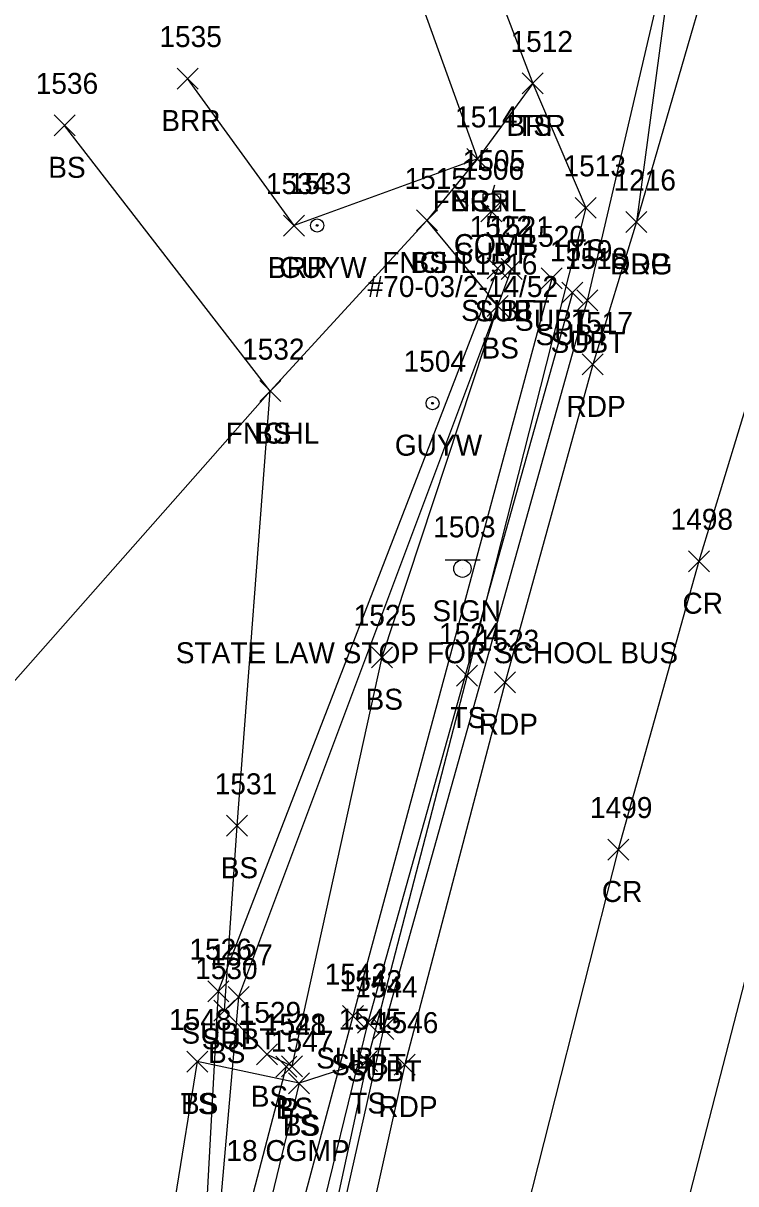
# Model space of a CAD drawing. Extents: x 1678863 to 1683592, y 407783 to 418211.
# Drawn here: x 1681241 to 1681308.9, y 417416.4 to 417527 of the extents above; entities that cross this region are included whole.
import ezdxf

# ---------------------------------------------------------------- set-up
doc = ezdxf.new("R2010")
doc.units = 0
for name, color, linetype in [('D_A', 7, 'Continuous'), ('D_C', 7, 'Continuous'), ('D_I', 7, 'Continuous'), ('D_TIC', 7, 'Continuous'), ('DCP', 7, 'Continuous'), ('L_A', 7, 'Continuous'), ('L_I', 7, 'Continuous'), ('L_TIC', 7, 'Continuous'), ('LABL', 7, 'Continuous'), ('LELB', 7, 'Continuous'), ('LFNC', 7, 'Continuous'), ('P_A', 7, 'Continuous'), ('P_I', 7, 'Continuous'), ('P_TIC', 7, 'Continuous'), ('PET', 7, 'Continuous'), ('PRC', 7, 'Continuous'), ('R_A', 7, 'Continuous'), ('R_I', 7, 'Continuous'), ('R_TIC', 7, 'Continuous'), ('RDG', 7, 'Continuous'), ('S_A', 7, 'Continuous'), ('S_C', 7, 'Continuous'), ('S_I', 7, 'Continuous'), ('SSGN', 7, 'Continuous'), ('U_A', 7, 'Continuous'), ('U_C', 7, 'Continuous'), ('U_I', 7, 'Continuous'), ('U_TIC', 7, 'Continuous'), ('UP', 7, 'Continuous'), ('UPGW', 7, 'Continuous'), ('UT', 7, 'Continuous')]:
    doc.layers.add(name, color=color, linetype=linetype)

msp = doc.modelspace()

# ---------------------------------------------------------------- linework, layer by layer
at = {"layer": 'D_TIC'}
for points in [[(1681265.09, 417426.61), (1681267.09, 417428.61)], [(1681267.09, 417426.61), (1681265.09, 417428.61)]]:
    msp.add_lwpolyline(points, dxfattribs=at)
at = {"layer": 'DCP'}
msp.add_lwpolyline([(1681266.09, 417427.61), (1681191.86, 417143.6)], dxfattribs=at)
at = {"layer": 'L_TIC'}
for points in [[(1681255.69, 417520.77), (1681257.69, 417522.77)], [(1681257.69, 417520.77), (1681255.69, 417522.77)], [(1681288.57, 417520.31), (1681290.57, 417522.31)], [(1681290.57, 417520.31), (1681288.57, 417522.31)], [(1681288.57, 417520.31), (1681290.57, 417522.31)], [(1681290.57, 417520.31), (1681288.57, 417522.31)], [(1681243.97, 417516.31), (1681245.97, 417518.31)], [(1681245.97, 417516.31), (1681243.97, 417518.31)], [(1681283.3, 417513.11), (1681285.3, 417515.11)], [(1681285.3, 417513.11), (1681283.3, 417515.11)], [(1681283.3, 417513.11), (1681285.3, 417515.11)], [(1681285.3, 417513.11), (1681283.3, 417515.11)], [(1681293.62, 417508.45), (1681295.62, 417510.45)], [(1681295.62, 417508.45), (1681293.62, 417510.45)], [(1681265.84, 417506.76), (1681267.84, 417508.76)], [(1681267.84, 417506.76), (1681265.84, 417508.76)], [(1681278.48, 417507.25), (1681280.48, 417509.25)], [(1681280.48, 417507.25), (1681278.48, 417509.25)], [(1681278.48, 417507.25), (1681280.48, 417509.25)], [(1681280.48, 417507.25), (1681278.48, 417509.25)], [(1681285.24, 417499.09), (1681287.24, 417501.09)], [(1681287.24, 417499.09), (1681285.24, 417501.09)], [(1681263.57, 417490.98), (1681265.57, 417492.98)], [(1681265.57, 417490.98), (1681263.57, 417492.98)], [(1681263.57, 417490.98), (1681265.57, 417492.98)], [(1681265.57, 417490.98), (1681263.57, 417492.98)], [(1681274.2, 417465.62), (1681276.2, 417467.62)], [(1681276.2, 417465.62), (1681274.2, 417467.62)], [(1681282.32, 417463.87), (1681284.32, 417465.87)], [(1681284.32, 417463.87), (1681282.32, 417465.87)], [(1681260.4, 417449.56), (1681262.4, 417451.56)], [(1681262.4, 417449.56), (1681260.4, 417451.56)], [(1681259.19, 417431.95), (1681261.19, 417433.95)], [(1681261.19, 417431.95), (1681259.19, 417433.95)], [(1681256.61, 417427.09), (1681258.61, 417429.09)], [(1681258.61, 417427.09), (1681256.61, 417429.09)], [(1681256.61, 417427.09), (1681258.61, 417429.09)], [(1681258.61, 417427.09), (1681256.61, 417429.09)], [(1681263.26, 417427.78), (1681265.26, 417429.78)], [(1681265.26, 417427.78), (1681263.26, 417429.78)], [(1681272.78, 417427.14), (1681274.78, 417429.14)], [(1681274.78, 417427.14), (1681272.78, 417429.14)], [(1681272.78, 417427.14), (1681274.78, 417429.14)], [(1681274.78, 417427.14), (1681272.78, 417429.14)], [(1681265.63, 417426.65), (1681267.63, 417428.65)], [(1681267.63, 417426.65), (1681265.63, 417428.65)], [(1681266.31, 417425.03), (1681268.31, 417427.03)], [(1681268.31, 417425.03), (1681266.31, 417427.03)], [(1681266.31, 417425.03), (1681268.31, 417427.03)], [(1681268.31, 417425.03), (1681266.31, 417427.03)]]:
    msp.add_lwpolyline(points, dxfattribs=at)
at = {"layer": 'LABL'}
msp.add_lwpolyline([(1681260.85, 417594.98), (1681276.66, 417555.15), (1681289.57, 417521.31), (1681284.3, 417514.11), (1681266.84, 417507.76), (1681256.69, 417521.77)], dxfattribs=at)
at = {"layer": 'LELB'}
for points in [[(1681289.57, 417521.31), (1681294.62, 417509.45), (1681283.32, 417464.87), (1681273.78, 417428.14), (1681267.14, 417397.31), (1681255.54, 417359.05)], [(1681279.48, 417508.25), (1681286.24, 417500.09), (1681275.2, 417466.62), (1681266.63, 417427.65), (1681264.26, 417428.78), (1681260.19, 417432.95), (1681261.4, 417450.56), (1681264.57, 417491.98), (1681244.97, 417517.31)], [(1681257.61, 417428.09), (1681253.33, 417401.8), (1681245.06, 417387.83)], [(1681273.78, 417428.14), (1681267.31, 417426.03), (1681257.61, 417428.09)], [(1681267.31, 417426.03), (1681260.9, 417399.5), (1681249.58, 417358.6), (1681240.31, 417323.2), (1681227.41, 417268.08), (1681222.89, 417241), (1681207.53, 417189.12), (1681197.87, 417155.68), (1681193.92, 417142.61), (1681187.71, 417132.19), (1681175.73, 417123.68)]]:
    msp.add_lwpolyline(points, dxfattribs=at)
at = {"layer": 'LFNC'}
msp.add_lwpolyline([(1681253.59, 417594.57), (1681270.41, 417552.71), (1681284.3, 417514.11), (1681279.48, 417508.25), (1681264.57, 417491.98), (1681233.36, 417456.67), (1681218.69, 417439.13)], dxfattribs=at)
at = {"layer": 'P_TIC'}
for points in [[(1681298.44, 417507.1), (1681300.44, 417509.1)], [(1681300.44, 417507.1), (1681298.44, 417509.1)], [(1681294.29, 417493.53), (1681296.29, 417495.53)], [(1681296.29, 417493.53), (1681294.29, 417495.53)], [(1681304.4, 417474.77), (1681306.4, 417476.77)], [(1681306.4, 417474.77), (1681304.4, 417476.77)], [(1681285.93, 417463.24), (1681287.93, 417465.24)], [(1681287.93, 417463.24), (1681285.93, 417465.24)], [(1681296.72, 417447.3), (1681298.72, 417449.3)], [(1681298.72, 417447.3), (1681296.72, 417449.3)], [(1681276.38, 417426.8), (1681278.38, 417428.8)], [(1681278.38, 417426.8), (1681276.38, 417428.8)]]:
    msp.add_lwpolyline(points, dxfattribs=at)
at = {"layer": 'PET'}
for points in [[(1681690.63, 417744.78), (1681670.87, 417745.33), (1681641.84, 417743.06), (1681615.24, 417740.75), (1681586.04, 417734.44), (1681571.71, 417731.87), (1681544.31, 417723.63), (1681517.23, 417711.83), (1681495.67, 417702.4), (1681484.34, 417696.04), (1681457.74, 417677.97), (1681437.33, 417662.92), (1681415.27, 417643.12), (1681390.03, 417616.29), (1681370.5, 417590.97), (1681353.64, 417562.95), (1681343.43, 417542.94), (1681335.68, 417524.63), (1681321.93, 417483.7), (1681311.58, 417442.86), (1681297.8, 417389.4), (1681289.83, 417351.74), (1681280.09, 417307.99)], [(1681346.12, 417609.33), (1681331.88, 417587.88), (1681320.86, 417568.4), (1681310.53, 417546.33), (1681299.44, 417508.1), (1681295.29, 417494.53), (1681286.93, 417464.24), (1681277.38, 417427.8), (1681270.21, 417395.58), (1681263.42, 417368.58), (1681252.88, 417321.59), (1681240.32, 417264.66)]]:
    msp.add_lwpolyline(points, dxfattribs=at)
at = {"layer": 'PRC'}
msp.add_lwpolyline([(1681689.28, 417758.12), (1681644.72, 417757.55), (1681604.93, 417753.08), (1681563.91, 417744.25), (1681526.24, 417731.47), (1681503.63, 417720.81), (1681486.3, 417712.13), (1681462.37, 417697.78), (1681439.98, 417682.26), (1681419.65, 417665.87), (1681392.79, 417639.13), (1681372.86, 417615.48), (1681356.04, 417592.08), (1681338.97, 417563.39), (1681323.96, 417530.56), (1681315.3, 417508.31), (1681305.4, 417475.77), (1681297.72, 417448.3), (1681287.9, 417409.62), (1681275.84, 417355.43), (1681267.02, 417318.48), (1681254.6, 417262.47)], dxfattribs=at)
at = {"layer": 'R_TIC'}
for points in [[(1681298.44, 417507.1), (1681300.44, 417509.1)], [(1681300.44, 417507.1), (1681298.44, 417509.1)]]:
    msp.add_lwpolyline(points, dxfattribs=at)
at = {"layer": 'RDG'}
msp.add_lwpolyline([(1681359.71, 417638.89), (1681351.39, 417629.69), (1681337.26, 417616.5), (1681319.44, 417594.5), (1681310.58, 417571.88), (1681304.84, 417548.33), (1681299.44, 417508.1)], dxfattribs=at)
at = {"layer": 'SSGN'}
for p, q in [((1681281.22, 417475.9), (1681284.56, 417475.9)), ((1681282.87, 417475.07), (1681282.87, 417475.07))]:
    msp.add_line(p, q, dxfattribs=at)
msp.add_circle((1681282.87, 417475.07), 0.833, dxfattribs=at)
at = {"layer": 'U_TIC'}
for points in [[(1681284.61, 417508.12), (1681286.61, 417510.12)], [(1681286.61, 417508.12), (1681284.61, 417510.12)], [(1681285.24, 417502.67), (1681287.24, 417504.67)], [(1681287.24, 417502.67), (1681285.24, 417504.67)], [(1681286.55, 417502.63), (1681288.55, 417504.63)], [(1681288.55, 417502.63), (1681286.55, 417504.63)], [(1681290.38, 417501.73), (1681292.38, 417503.73)], [(1681292.38, 417501.73), (1681290.38, 417503.73)], [(1681292.34, 417500.36), (1681294.34, 417502.36)], [(1681294.34, 417500.36), (1681292.34, 417502.36)], [(1681293.76, 417499.63), (1681295.76, 417501.63)], [(1681295.76, 417499.63), (1681293.76, 417501.63)], [(1681258.61, 417433.8), (1681260.61, 417435.8)], [(1681260.61, 417433.8), (1681258.61, 417435.8)], [(1681260.54, 417433.26), (1681262.54, 417435.26)], [(1681262.54, 417433.26), (1681260.54, 417435.26)], [(1681271.44, 417431.43), (1681273.44, 417433.43)], [(1681273.44, 417431.43), (1681271.44, 417433.43)], [(1681272.86, 417430.8), (1681274.86, 417432.8)], [(1681274.86, 417430.8), (1681272.86, 417432.8)], [(1681274.35, 417430.21), (1681276.35, 417432.21)], [(1681276.35, 417430.21), (1681274.35, 417432.21)]]:
    msp.add_lwpolyline(points, dxfattribs=at)
at = {"layer": 'UP'}
for p, q in [((1681285.92, 417511.62), (1681285.67, 417510.79)), ((1681284.83, 417509.12), (1681284.83, 417510.79)), ((1681284.83, 417510.79), (1681286.5, 417510.79)), ((1681285.67, 417509.95), (1681285.67, 417509.95)), ((1681286.5, 417510.79), (1681286.5, 417509.12)), ((1681286.5, 417509.12), (1681284.83, 417509.12)), ((1681285.42, 417508.29), (1681285.67, 417509.12))]:
    msp.add_line(p, q, dxfattribs=at)
msp.add_circle((1681285.67, 417509.95), 0.833, dxfattribs=at)
at = {"layer": 'UPGW'}
for centre, radius in [((1681269.03, 417507.77), 0.625), ((1681269.03, 417507.77), 0.0833), ((1681280.03, 417490.83), 0.625), ((1681280.03, 417490.83), 0.0833)]:
    msp.add_circle(centre, radius, dxfattribs=at)
at = {"layer": 'UT'}
for points in [[(1681381.64, 417894.86), (1681369.44, 417851.23), (1681362.77, 417839.77), (1681348.63, 417793.11), (1681339.41, 417740.3), (1681338.81, 417692.78), (1681334.81, 417671.92), (1681316.38, 417593.31), (1681294.76, 417500.63), (1681275.35, 417431.21), (1681265.74, 417388.38), (1681249.51, 417317.18)], [(1681286.24, 417503.67), (1681259.61, 417434.8), (1681257.23, 417390.84), (1681241.33, 417320.54)], [(1681287.55, 417503.63), (1681261.54, 417434.26), (1681257.73, 417390.8), (1681242.22, 417319.94)], [(1681291.38, 417502.73), (1681272.44, 417432.43), (1681261.04, 417389.78), (1681244.72, 417319.22)], [(1681293.34, 417501.36), (1681273.86, 417431.8), (1681263.37, 417389), (1681246.28, 417318.71)]]:
    msp.add_lwpolyline(points, dxfattribs=at)

# ---------------------------------------------------------------- texts
at = {"layer": 'D_A'}
msp.add_text('P', height=2, dxfattribs=at).set_placement((1681265.47, 417422.61))
at = {"layer": 'D_C'}
msp.add_text('18 CGMP', height=2, dxfattribs=at).set_placement((1681260.38, 417418.61))
at = {"layer": 'D_I'}
msp.add_text('1541', height=2, dxfattribs=at).set_placement((1681263.97, 417430.61))
at = {"layer": 'L_A'}
for s, p in [('BRR', (1681254.18, 417516.77)), ('BRR', (1681287.06, 417516.31)), ('TS', (1681287.98, 417516.31)), ('BS', (1681243.41, 417512.31)), ('FNCHL', (1681280.04, 417509.11)), ('BRR', (1681281.78, 417509.11)), ('TS', (1681293.03, 417504.45)), ('BRR', (1681264.33, 417502.76)), ('FNCHL', (1681275.23, 417503.25)), ('BS', (1681277.92, 417503.25)), ('BS', (1681284.68, 417495.09)), ('FNCHL', (1681260.32, 417486.98)), ('BS', (1681263.01, 417486.98)), ('BS', (1681273.64, 417461.62)), ('TS', (1681281.73, 417459.87)), ('BS', (1681259.84, 417445.56)), ('BS', (1681258.63, 417427.95)), ('BS', (1681262.7, 417423.78)), ('TS', (1681256.02, 417423.09)), ('BS', (1681256.05, 417423.09)), ('BS', (1681265.07, 417422.65)), ('TS', (1681272.19, 417423.14)), ('TS', (1681272.19, 417423.14)), ('TS', (1681265.72, 417421.03)), ('BS', (1681265.75, 417421.03))]:
    msp.add_text(s, height=2, dxfattribs=at).set_placement(p)
at = {"layer": 'L_I'}
for s, p in [('1535', (1681254, 417524.77)), ('1512', (1681287.45, 417524.31)), ('1512', (1681287.45, 417524.31)), ('1536', (1681242.22, 417520.31)), ('1514', (1681282.17, 417517.11)), ('1514', (1681282.17, 417517.11)), ('1513', (1681292.5, 417512.45)), ('1515', (1681277.35, 417511.25)), ('1515', (1681277.35, 417511.25)), ('1534', (1681264.14, 417510.76)), ('1516', (1681284.06, 417503.09)), ('1532', (1681261.88, 417494.98)), ('1532', (1681261.88, 417494.98)), ('1525', (1681272.51, 417469.62)), ('1524', (1681280.63, 417467.87)), ('1531', (1681259.27, 417453.56)), ('1530', (1681257.41, 417435.95)), ('1529', (1681261.56, 417431.78)), ('1548', (1681254.92, 417431.09)), ('1548', (1681254.92, 417431.09)), ('1528', (1681263.93, 417430.65)), ('1545', (1681271.08, 417431.14)), ('1545', (1681271.08, 417431.14)), ('1547', (1681264.62, 417429.03)), ('1547', (1681264.62, 417429.03))]:
    msp.add_text(s, height=2, dxfattribs=at).set_placement(p)
at = {"layer": 'P_A'}
for s, p in [('RDP', (1681296.93, 417503.1)), ('RDP', (1681292.78, 417489.53)), ('CR', (1681303.83, 417470.77)), ('RDP', (1681284.42, 417459.24)), ('CR', (1681296.15, 417443.3)), ('RDP', (1681274.86, 417422.8))]:
    msp.add_text(s, height=2, dxfattribs=at).set_placement(p)
at = {"layer": 'P_I'}
for s, p in [('1216', (1681297.26, 417511.1)), ('1517', (1681293.17, 417497.53)), ('1498', (1681302.7, 417478.77)), ('1523', (1681284.24, 417467.24)), ('1499', (1681295.02, 417451.3)), ('1546', (1681274.63, 417430.8))]:
    msp.add_text(s, height=2, dxfattribs=at).set_placement(p)
at = {"layer": 'R_A'}
msp.add_text('DRG', height=2, dxfattribs=at).set_placement((1681296.93, 417503.1))
at = {"layer": 'R_I'}
msp.add_text('1216', height=2, dxfattribs=at).set_placement((1681297.26, 417511.1))
at = {"layer": 'S_A'}
msp.add_text('SIGN', height=2, dxfattribs=at).set_placement((1681280.01, 417470.05))
at = {"layer": 'S_C'}
msp.add_text('STATE LAW STOP FOR SCHOOL BUS', height=2, dxfattribs=at).set_placement((1681255.56, 417466.05))
at = {"layer": 'S_I'}
msp.add_text('1503', height=2, dxfattribs=at).set_placement((1681280.08, 417478.05))
at = {"layer": 'U_A'}
for s, p in [('COMB', (1681282.05, 417504.95)), ('SUBT', (1681282.11, 417504.12)), ('GUYW', (1681265.43, 417502.77)), ('SUBT', (1681282.74, 417498.67)), ('SUBT', (1681284.05, 417498.63)), ('SUBT', (1681287.88, 417497.73)), ('SUBT', (1681289.84, 417496.36)), ('SUBT', (1681291.26, 417495.63)), ('GUYW', (1681276.43, 417485.83)), ('SUBT', (1681256.1, 417429.8)), ('SUBT', (1681258.04, 417429.26)), ('SUBT', (1681268.94, 417427.43)), ('SUBT', (1681270.36, 417426.8)), ('SUBT', (1681271.84, 417426.21))]:
    msp.add_text(s, height=2, dxfattribs=at).set_placement(p)
at = {"layer": 'U_C'}
msp.add_text('#70-03/2-14/52', height=2, dxfattribs=at).set_placement((1681273.84, 417500.95))
at = {"layer": 'U_I'}
for s, p in [('1505', (1681282.89, 417512.95)), ('1506', (1681282.79, 417512.12)), ('1533', (1681266.34, 417510.77)), ('1522', (1681283.55, 417506.67)), ('1521', (1681285.43, 417506.63)), ('1520', (1681288.6, 417505.73)), ('1519', (1681291.21, 417504.36)), ('1518', (1681292.64, 417503.63)), ('1504', (1681277.26, 417493.83)), ('1526', (1681256.86, 417437.8)), ('1527', (1681258.85, 417437.26)), ('1542', (1681269.75, 417435.43)), ('1543', (1681271.17, 417434.8)), ('1544', (1681272.65, 417434.21))]:
    msp.add_text(s, height=2, dxfattribs=at).set_placement(p)

doc.saveas('drawing.dxf')
